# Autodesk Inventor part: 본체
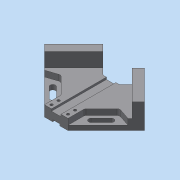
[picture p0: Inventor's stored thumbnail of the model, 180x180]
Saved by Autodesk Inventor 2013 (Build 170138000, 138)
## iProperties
Created: 2019-04
Part Number: 본체
Material: 일반
Document SubType Name: Modeling
Designer: dgall
Density: 1 g/cm^3
Author: dgall
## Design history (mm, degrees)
sketch "스케치1"
  geometry: L1 (0, 0)-(84.853, 84.853); L2 (84.853, 84.853)-(169.706, 0); L3 (169.706, 0)-(84.853, -84.853); L4 (84.853, -84.853)-(0, 0); L5 (64.853, -64.853)-(104.853, -64.853); L6 (0, 0)-(64.853, -64.853); L7 (169.706, 0)-(104.853, -64.853)
  constraints: 14 end point, 3 perpendicular, 2 collinear, 2 point on line, 1 horizontal, 1 horizontal alignment
  dimensions: "d0" = 120 distance of L1.start L1.end; "d1" = 120 distance of L1.end L2.end; "d2" = 40 distance of L5.start L5.end
extrude "돌출1" new body sketch "스케치1" distance "d3" = 42; taper "d4" = 0 deg
sketch "스케치2"
  geometry: L1 (84.853, 84.853)-(0, 0) reference; L2 (64.853, -64.853)-(104.853, -64.853) reference; L3 (169.706, 0)-(84.853, 84.853) reference; L4 (49.497, 49.497)-(70.853, 28.142); L5 (120.208, 49.497)-(84.853, 14.142); L6 (70.853, 28.142)-(98.853, 28.142); L7 (98.853, 28.142)-(120.208, 49.497)
  constraints: 8 end point, 3 point on line, 1 collinear, 1 horizontal alignment, 1 parallel, 1 perpendicular
  dimensions: "d6" = 50 distance of L5.start L5.end; "d8" = 28 distance of L4.end L6.end
extrude "돌출2" cut sketch "스케치2" distance "d9" = 103.75; taper "d10" = 0 deg
sketch "스케치3"
  geometry: L1 (91.716, 0)-(0, 0) reference; L2 (61.515, 0)-(91.716, 0) reference; L3 (76.716, 0)-(76.716, 24); L4 (76.716, 24)-(-28.284, 24); L5 (76.716, 0)-(-28.284, 0); L6 (0, 0)-(-28.284, 0) reference; L7 (-28.284, 0)-(-28.284, 24)
  constraints: 8 end point, 3 perpendicular, 1 collinear, 1 point on line
  dimensions: "d11" = 15 distance of L1.start L3.start; "d12" = 24 distance of L3.start L3.end
extrude "돌출3" cut sketch "스케치3" distance "d13" = 103.75; taper "d14" = 0 deg
sketch "스케치4"
  geometry: L1 (16.25, 0)-(0, 0) reference; L2 (16.25, 0)-(16.25, 24) reference; L3 (0, 0)-(15, 0); L4 (15, 0)-(15, 24); L5 (15, 24)-(16.25, 24); 1 further point
  constraints: 6 end point, 2 perpendicular, 1 point on line
  dimensions: "d15" = 15 distance of L1.end L3.end
extrude "돌출4" cut sketch "스케치4" distance "d16" = 103.75; taper "d17" = 0 deg
sketch "스케치5"
  geometry: L1 (6, 18)-(34, 18) reference; L2 (20, 18)-(20, 14.5); L3 (20, 14.5)-(12, 14.5); L4 (20, 14.5)-(28, 14.5); L5 (12, 14.5)-(12, 18); L6 (28, 14.5)-(28, 18); 1 further point
  constraints: 10 end point, 4 perpendicular, 2 point on line, 1 collinear, 1 midpoint
  dimensions: "d18" = 3.5 distance of L2.start L2.end; "d20" = 8 distance of L2.end L3.end; "d21" = 8 distance of L2.end L4.end
extrude "돌출5" cut sketch "스케치5" distance "d22" = 103.75; taper "d23" = 0 deg
sketch "스케치6"
  geometry: L1 (40, 0)-(0, 0) reference; L2 (28, 14.5)-(12, 14.5) reference; L3 (20, 0)-(20, 3); L4 (20, 3)-(14, 3); L5 (20, 3)-(26, 3); L6 (14, 3)-(14, 0); L7 (26, 3)-(26, 0); 1 further point
  constraints: 10 end point, 4 perpendicular, 2 point on line, 1 collinear, 1 midpoint
  dimensions: "d24" = 3 distance of L3.start L3.end; "d26" = 6 distance of L3.end L4.end; "d27" = 6 distance of L3.end L5.end
extrude "돌출6" cut sketch "스케치6" distance "d28" = 103.75; taper "d29" = 0 deg
sketch "스케치7"
  geometry: L1 (12, 0)-(0, 0) reference; L2 (28, 0)-(12, 0) reference; L3 (20, 0)-(6, 0); L4 (6, 0)-(6, 6); L5 (6, 6)-(6, 18); L6 (20, 0)-(34, 0); L7 (40, 0)-(28, 0) reference; L8 (20, 0)-(20, 12); C1 r 2.25 at (6, 6); C2 r 2.25 at (6, 18); C3 r 2.25 at (34, 18); C4 r 2.25 at (34, 6); 1 further point
  constraints: 10 end point, 4 centre point, 3 midpoint, 2 coincident, 2 perpendicular, 2 symmetric about line, 1 collinear, 2 other
  dimensions: "d30" = 6 distance of L3.end L4.end; "d32" = 4.5 diameter of C1; "d33" = 12 distance of L5.start L5.end; "d34" = 4.5 diameter of C2
extrude "돌출7" cut sketch "스케치7" distance "d35" = 8; taper "d36" = 0 deg
sketch "스케치8"
  geometry: L1 (-78.853, -64.853)-(-90.853, -64.853) reference; L2 (-84.853, -64.853)-(-70.853, -64.853); L3 (-76.853, -64.853)-(-64.853, -64.853) reference; L4 (-84.853, -64.853)-(-98.853, -64.853); L5 (-104.853, -64.853)-(-92.853, -64.853) reference; L6 (-98.853, -64.853)-(-98.853, -58.853); L7 (-98.853, -58.853)-(-98.853, -46.853); L8 (-84.853, -64.853)-(-84.853, -54.853); C1 r 4 at (-98.853, -58.853); C2 r 4 at (-98.853, -46.853); C3 r 4 at (-70.853, -46.853); C4 r 4 at (-70.853, -58.853)
  constraints: 10 end point, 4 centre point, 3 midpoint, 2 coincident, 2 symmetric about line, 1 collinear, 1 parallel, 1 perpendicular, 2 other
  dimensions: "d37" = 12 distance of L7.start L7.end; "d39" = 8 diameter of C2; "d40" = 8 diameter of C1
extrude "돌출8" cut sketch "스케치8" distance "d41" = 10; taper "d42" = 0 deg
sketch "스케치9"
  geometry: L1 (-64.853, 64.853)-(-57.782, 71.924); L2 (-64.853, 64.853)-(-15.355, 114.35) reference; L3 (-57.782, 71.924)-(-29.497, 43.64); L4 (-29.497, 43.64)-(-12.527, 26.669); L5 (-32.679, 40.458)-(-15.709, 23.487); L6 (-26.315, 46.822)-(-9.345, 29.851); L7 (14, 0)-(26, 0) reference; L8 (20, 0)-(20, 15.75); L9 (66.315, 46.822)-(49.345, 29.851); L10 (72.679, 40.458)-(55.709, 23.487); A1 r 4.5 centre (-29.497, 43.64) between (-26.315, 46.822) and (-32.679, 40.458); A2 r 4.5 centre (-12.527, 26.669) between (-15.709, 23.487) and (-9.345, 29.851); A3 r 4.5 centre (69.497, 43.64) between (72.679, 40.458) and (66.315, 46.822); A4 r 4.5 centre (52.527, 26.669) between (49.345, 29.851) and (55.709, 23.487)
  constraints: 16 end point, 8 point on circle, 6 symmetric about line, 4 centre point, 2 coincident, 2 parallel, 2 perpendicular, 2 tangent, 1 collinear, 1 midpoint, 1 point on line, 2 other
  dimensions: "d43" = 10 distance of L1.start L1.end; "d44" = 40 distance of L1.end L3.end; "d45" = 9 diameter of A1; "d46" = 24 distance of L4.start L4.end; "d47" = 9 diameter of A2
extrude "돌출9" cut sketch "스케치9" distance "d48" = 48; taper "d49" = 0 deg
sketch "스케치10"
  geometry: L1 (-15.709, 23.487)-(-32.679, 40.458) reference; L2 (-26.315, 46.822)-(-9.345, 29.851) reference; L3 (0, 0)-(-54.246, 54.246) reference; L4 (12, 0)-(0, 0) reference; L5 (-64.853, 64.853)-(-50.711, 50.711); L6 (-43.64, 43.64)-(-29.497, 57.782); L7 (-29.497, 57.782)-(-50.711, 50.711); L8 (0, 0)-(0, 28.284); L9 (14, 0)-(26, 0) reference; L10 (-29.497, 57.782)-(0, 28.284); L11 (20, 0)-(20, 20.25); L12 (69.497, 57.782)-(90.711, 50.711); L13 (69.497, 57.782)-(40, 28.284); L14 (40, 0)-(40, 28.284); L15 (90.711, 50.711)-(40, 0); L16 (94.246, 54.246)-(40, 0) reference; A1 r 4.5 centre (-29.497, 43.64) between (-26.315, 46.822) and (-32.679, 40.458) reference; A2 r 4.5 centre (-12.527, 26.669) between (-15.709, 23.487) and (-9.345, 29.851) reference
  constraints: 20 end point, 4 perpendicular, 4 symmetric about line, 2 point on line, 1 collinear, 1 midpoint
  dimensions: "d50" = 20 distance of L5.start L5.end; "d51" = 30 distance of L6.start L5.start; "d52" = 20 distance of L6.start L6.end
extrude "돌출10" cut sketch "스케치10" distance "d53" = 10; taper "d54" = 0 deg
fillet "모깎기1" dims "d55" = 5
node "솔리드1"
